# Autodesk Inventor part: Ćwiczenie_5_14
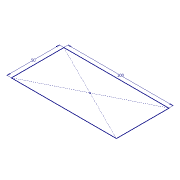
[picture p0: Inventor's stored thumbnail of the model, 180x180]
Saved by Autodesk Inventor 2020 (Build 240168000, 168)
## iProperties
Created: 2005-02
Part Number: Ćwiczenie_5_14
Document SubType Name: Modeling
Designer: F.Stasiak
Manufacturer: Standard
Standards Organization: Custom
Density: 1 g/cm^3
Material: Ogólny
Appearance: Domyślna
Manager: www.cadconsulting.pl
Company: Fabian Stasiak CAD Consulting
Author: F.Stasiak
Subject: Zbiór ćwiczeń. Autodesk Inventor 2020. Kurs podstawowy
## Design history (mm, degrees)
sketch "Szkic1"
  geometry: L1 (50, -25)-(-50, -25); L2 (-50, -25)-(-50, 25); L3 (-50, 25)-(50, 25); L4 (50, 25)-(50, -25); L5 (50, -25)-(-50, 25); L6 (-50, -25)-(50, 25); 2 further points
  constraints: 12 end point, 2 midpoint, 2 parallel, 1 coincident, 1 horizontal, 1 perpendicular
  dimensions: "d2" = 100 dimension on point (0, 0) point (0, 0) L1.start L2.end L1.end L3.end L1 L2 L3 L4 L5 L6; "d2" = 100 distance of L2.end L3.end; "d3" = 50 distance of L1.end L2.end
node "Korpusy bryłowe"
node "Korpusy powierzchniowe"
